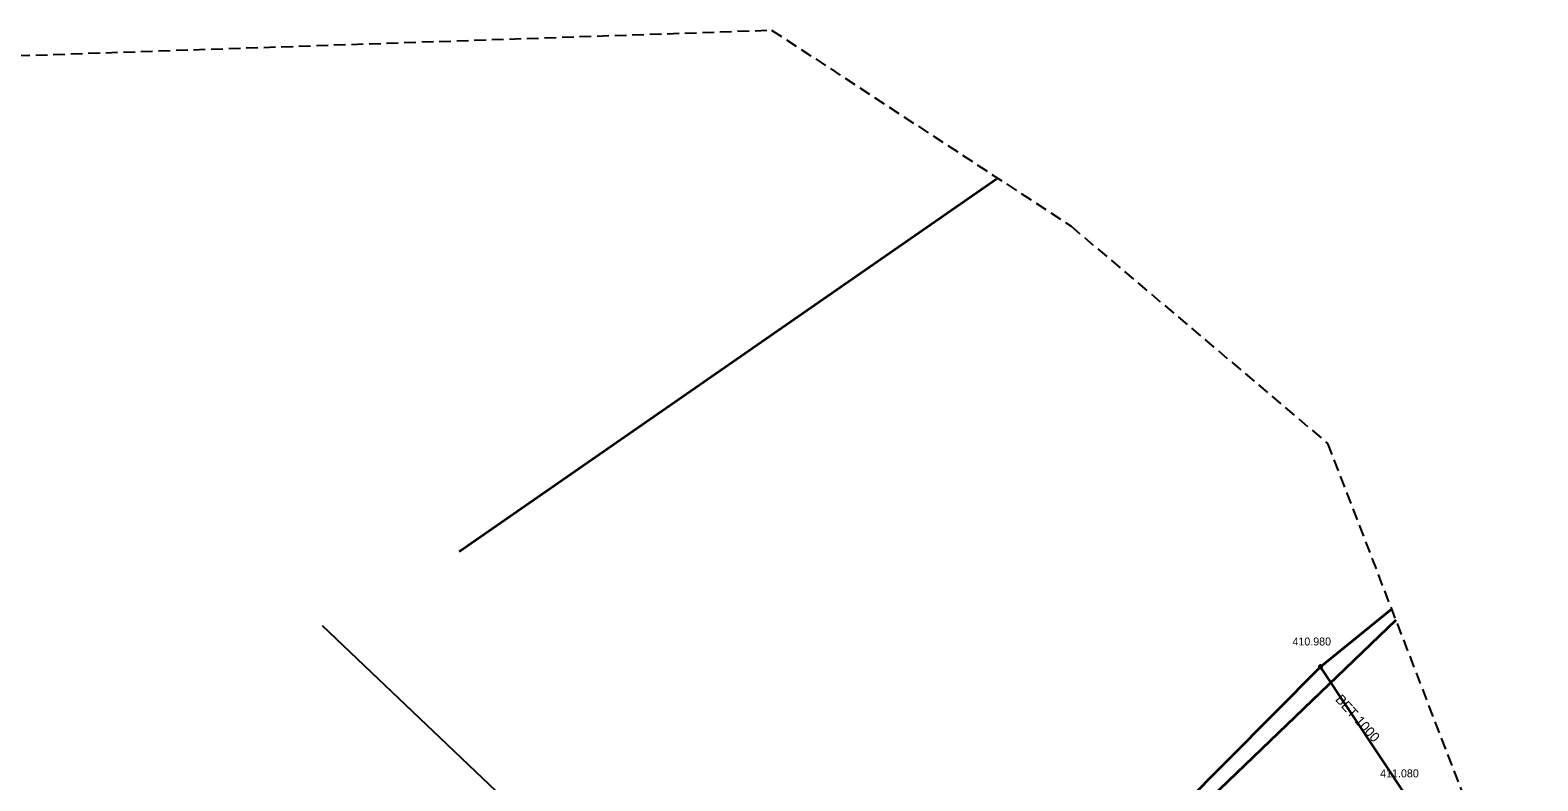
# Model space of a CAD drawing. Extents: x -867104 to -866746, y -1014489 to -1014255.
# Drawn here: x -866916.3 to -866746.2, y -1014339.3 to -1014254.6 of the extents above; entities that cross this region are included whole.
import ezdxf

# ---------------------------------------------------------------- set-up
doc = ezdxf.new("R2010")
doc.units = 0
doc.header["$LTSCALE"] = 0.44
doc.linetypes.add('MEDIUM_DASHED', pattern=[4.5, 3, -1.5])
for name, color, linetype, lineweight in [('1', 7, 'Continuous', 35), ('21', 7, 'Continuous', 35), ('3', 7, 'Continuous', 25), ('32', 7, 'Continuous', 13), ('62', 7, 'MEDIUM_DASHED', 25)]:
    doc.layers.add(name, color=color, linetype=linetype, lineweight=lineweight)

msp = doc.modelspace()

# ---------------------------------------------------------------- linework, layer by layer
at = {"layer": '1'}
msp.add_lwpolyline([(-866762.254, -1014321.165), (-866822.841, -1014379.375), (-866840.01, -1014396.11)], dxfattribs=at)
at = {"layer": '21'}
for p, q in [((-866867.906, -1014313.414), (-866807.168, -1014271.27)), ((-866770.762, -1014326.42), (-866762.74, -1014319.906)), ((-866760.867, -1014341.297), (-866770.762, -1014326.42))]:
    msp.add_line(p, q, dxfattribs=at)
msp.add_lwpolyline([(-866846.197, -1014404.673), (-866828.183, -1014384.303), (-866770.762, -1014326.42)], dxfattribs=at)
at = {"layer": '3'}
msp.add_lwpolyline([(-866822.842, -1014379.376), (-866822.91, -1014379.31), (-866883.327, -1014321.768)], dxfattribs=at)
at = {"layer": '32'}
for points in [[(-866770.531, -1014326.42), (-866770.537, -1014326.368), (-866770.554, -1014326.318), (-866770.583, -1014326.274), (-866770.62, -1014326.237), (-866770.665, -1014326.21), (-866770.715, -1014326.193), (-866770.768, -1014326.189), (-866770.82, -1014326.196), (-866770.869, -1014326.215), (-866770.912, -1014326.244), (-866770.948, -1014326.283), (-866770.974, -1014326.328), (-866770.99, -1014326.379), (-866770.993, -1014326.431), (-866770.985, -1014326.483), (-866770.965, -1014326.532), (-866770.934, -1014326.575), (-866770.895, -1014326.609), (-866770.849, -1014326.635), (-866770.798, -1014326.649), (-866770.745, -1014326.651), (-866770.694, -1014326.641), (-866770.646, -1014326.62), (-866770.603, -1014326.589), (-866770.569, -1014326.548), (-866770.545, -1014326.502), (-866770.532, -1014326.451)], [(-866770.561, -1014326.42), (-866770.567, -1014326.371), (-866770.584, -1014326.325), (-866770.612, -1014326.285), (-866770.649, -1014326.253), (-866770.693, -1014326.231), (-866770.741, -1014326.22), (-866770.79, -1014326.22), (-866770.837, -1014326.233), (-866770.88, -1014326.257), (-866770.916, -1014326.29), (-866770.943, -1014326.331), (-866770.959, -1014326.378), (-866770.963, -1014326.427), (-866770.956, -1014326.475), (-866770.937, -1014326.52), (-866770.907, -1014326.56), (-866770.869, -1014326.591), (-866770.825, -1014326.611), (-866770.777, -1014326.621), (-866770.728, -1014326.619), (-866770.681, -1014326.604), (-866770.638, -1014326.579), (-866770.603, -1014326.545), (-866770.578, -1014326.503), (-866770.564, -1014326.456)], [(-866770.591, -1014326.42), (-866770.597, -1014326.375), (-866770.614, -1014326.333), (-866770.642, -1014326.298), (-866770.678, -1014326.271), (-866770.72, -1014326.254), (-866770.765, -1014326.249), (-866770.809, -1014326.255), (-866770.851, -1014326.274), (-866770.886, -1014326.302), (-866770.913, -1014326.339), (-866770.929, -1014326.381), (-866770.933, -1014326.426), (-866770.926, -1014326.471), (-866770.907, -1014326.512), (-866770.878, -1014326.546), (-866770.841, -1014326.572), (-866770.798, -1014326.588), (-866770.753, -1014326.591), (-866770.708, -1014326.583), (-866770.668, -1014326.563), (-866770.634, -1014326.534), (-866770.608, -1014326.496), (-866770.594, -1014326.453)], [(-866770.621, -1014326.42), (-866770.625, -1014326.379), (-866770.644, -1014326.342), (-866770.671, -1014326.311), (-866770.706, -1014326.29), (-866770.746, -1014326.279), (-866770.787, -1014326.281), (-866770.826, -1014326.294), (-866770.86, -1014326.318), (-866770.885, -1014326.35), (-866770.9, -1014326.388), (-866770.902, -1014326.429), (-866770.895, -1014326.469), (-866770.875, -1014326.505), (-866770.846, -1014326.534), (-866770.809, -1014326.553), (-866770.769, -1014326.561), (-866770.728, -1014326.557), (-866770.69, -1014326.542), (-866770.657, -1014326.516), (-866770.635, -1014326.482), (-866770.622, -1014326.443)], [(-866770.651, -1014326.42), (-866770.656, -1014326.384), (-866770.674, -1014326.352), (-866770.7, -1014326.327), (-866770.733, -1014326.312), (-866770.77, -1014326.309), (-866770.804, -1014326.317), (-866770.836, -1014326.337), (-866770.858, -1014326.365), (-866770.872, -1014326.399), (-866770.872, -1014326.436), (-866770.861, -1014326.471), (-866770.84, -1014326.5), (-866770.809, -1014326.521), (-866770.775, -1014326.531), (-866770.738, -1014326.529), (-866770.704, -1014326.515), (-866770.677, -1014326.492), (-866770.657, -1014326.46), (-866770.651, -1014326.425)], [(-866770.681, -1014326.42), (-866770.686, -1014326.389), (-866770.703, -1014326.363), (-866770.728, -1014326.346), (-866770.759, -1014326.339), (-866770.79, -1014326.343), (-866770.817, -1014326.36), (-866770.835, -1014326.384), (-866770.843, -1014326.415), (-866770.839, -1014326.445), (-866770.824, -1014326.473), (-866770.799, -1014326.492), (-866770.77, -1014326.501), (-866770.739, -1014326.498), (-866770.711, -1014326.484), (-866770.691, -1014326.46), (-866770.681, -1014326.431)], [(-866770.711, -1014326.42), (-866770.716, -1014326.396), (-866770.733, -1014326.378), (-866770.755, -1014326.369), (-866770.78, -1014326.372), (-866770.801, -1014326.386), (-866770.812, -1014326.408), (-866770.812, -1014326.433), (-866770.799, -1014326.454), (-866770.78, -1014326.468), (-866770.755, -1014326.471), (-866770.732, -1014326.462), (-866770.716, -1014326.444)], [(-866770.741, -1014326.42), (-866770.746, -1014326.405), (-866770.761, -1014326.399), (-866770.776, -1014326.403), (-866770.782, -1014326.417), (-866770.779, -1014326.432), (-866770.766, -1014326.441), (-866770.75, -1014326.438), (-866770.741, -1014326.426)]]:
    msp.add_lwpolyline(points, close=True, dxfattribs=at)
at = {"layer": '62'}
msp.add_lwpolyline([(-867100.742, -1014391.242), (-867092.704, -1014271.063), (-867058.137, -1014262.221), (-866832.652, -1014254.584), (-866798.889, -1014276.691), (-866769.95, -1014301.209), (-866746.236, -1014362.705), (-866806.526, -1014433.445), (-866883.697, -1014488.912), (-866958.859, -1014435.455)], close=True, dxfattribs=at)

# ---------------------------------------------------------------- texts
at = {"layer": '1'}
for s, p in [('410.980 ', (-866773.911, -1014324.004)), ('411.080 ', (-866764.016, -1014338.881))]:
    msp.add_text(s, height=0.9, dxfattribs=at).set_placement(p)
msp.add_text('BET 1000', height=1.1, rotation=312, dxfattribs=at).set_placement((-866769.151, -1014330.148))

doc.saveas('drawing.dxf')
